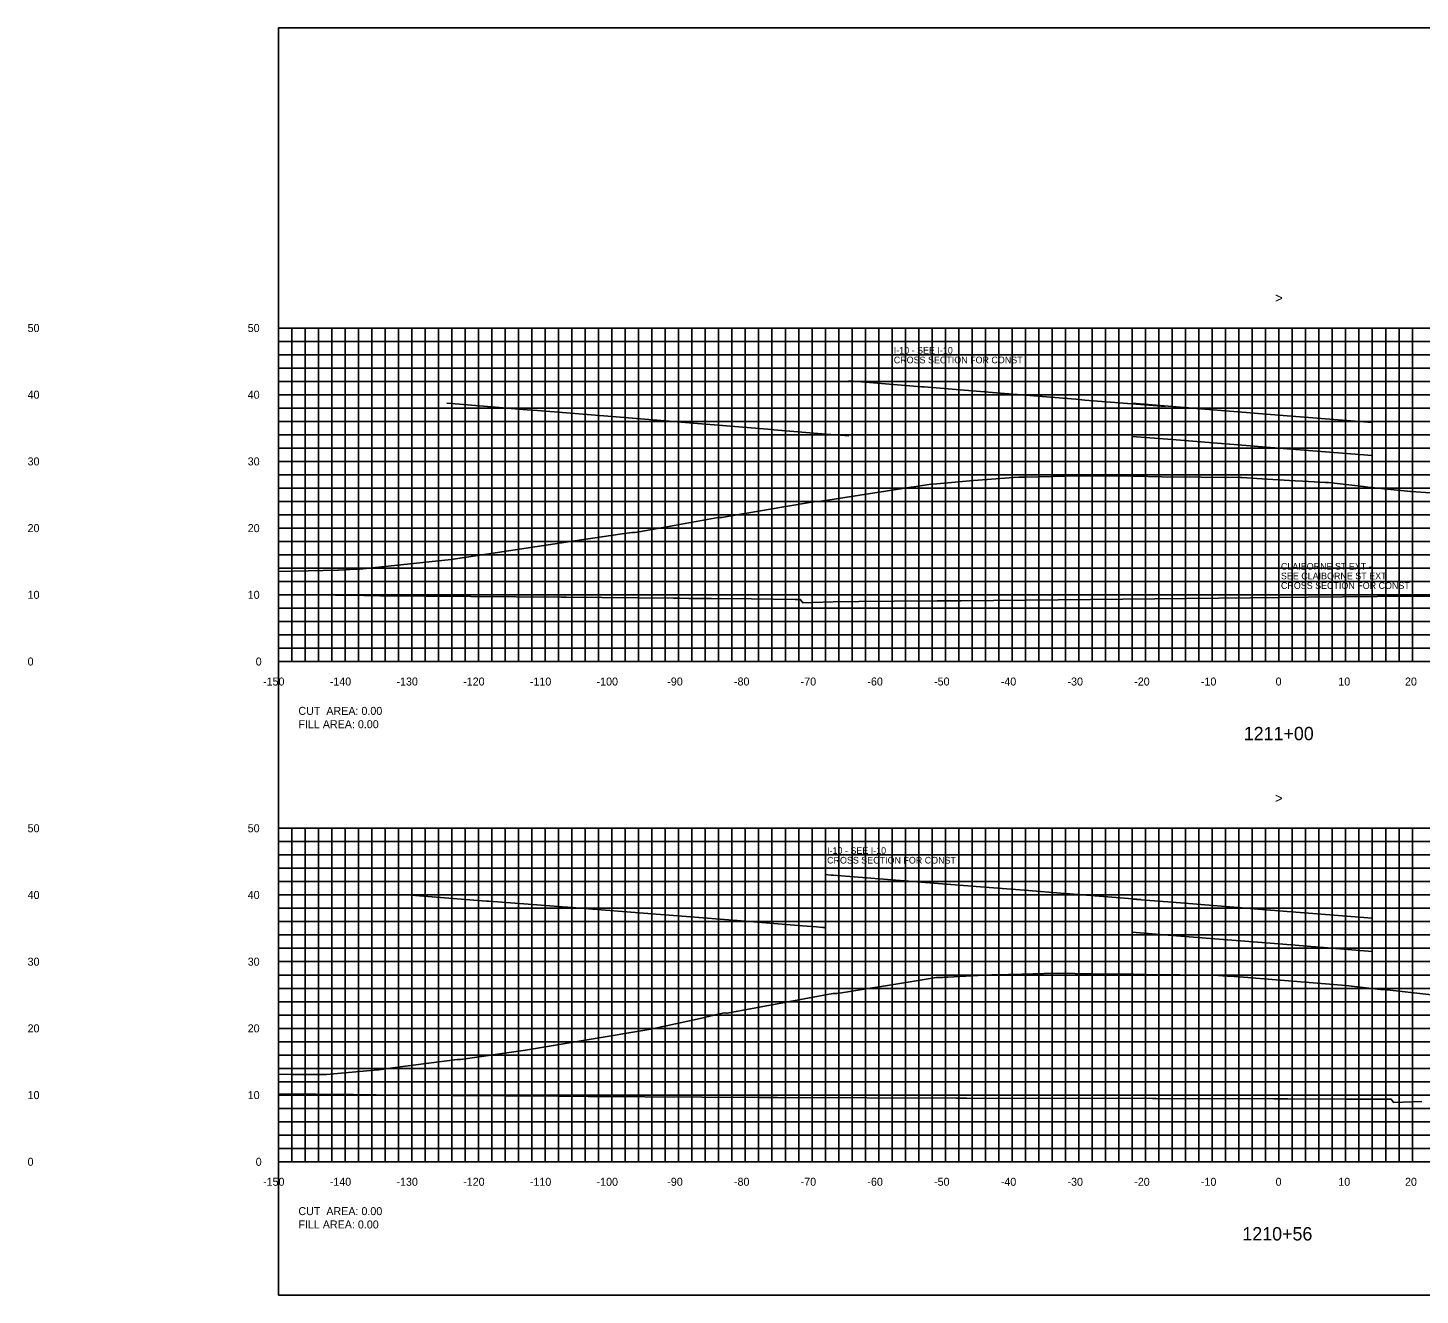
# Model space of a CAD drawing. Extents: x 1797305 to 1804485, y 245831 to 250849.
# Drawn here: x 1804143.4 to 1804352.2, y 250079.4 to 250269.4 of the extents above; entities that cross this region are included whole.
import ezdxf

# ---------------------------------------------------------------- set-up
doc = ezdxf.new("R2010")
doc.units = 0
for name, color, linetype in [('1', 7, 'Continuous'), ('10', 7, 'Continuous'), ('29', 7, 'Continuous'), ('60', 7, 'Continuous'), ('CL-CNST', 7, 'Continuous'), ('EDPV-LINE', 7, 'Continuous'), ('Level 31', 7, 'Continuous'), ('LIMT-CSLINE', 7, 'Continuous'), ('M-ROADS', 7, 'Continuous'), ('SURVEY - DRAINAGE - Area Shapes', 7, 'Continuous')]:
    doc.layers.add(name, color=color, linetype=linetype)

msp = doc.modelspace()

# ---------------------------------------------------------------- linework, layer by layer
msp.add_lwpolyline([(1804181, 250079.43), (1804481, 250079.43), (1804481, 250269.43), (1804181, 250269.43)], close=True)
at = {"layer": '29'}
for p, q in [((1804181, 250224.43), (1804481, 250224.43)), ((1804181, 250174.43), (1804181, 250224.43)), ((1804183, 250174.43), (1804183, 250224.43)), ((1804185, 250174.43), (1804185, 250224.43)), ((1804187, 250174.43), (1804187, 250224.43)), ((1804189, 250174.43), (1804189, 250224.43)), ((1804191, 250174.43), (1804191, 250224.43)), ((1804193, 250174.43), (1804193, 250224.43)), ((1804195, 250174.43), (1804195, 250224.43)), ((1804197, 250174.43), (1804197, 250224.43)), ((1804199, 250174.43), (1804199, 250224.43)), ((1804201, 250174.43), (1804201, 250224.43)), ((1804203, 250174.43), (1804203, 250224.43)), ((1804205, 250174.43), (1804205, 250224.43)), ((1804207, 250174.43), (1804207, 250224.43)), ((1804209, 250174.43), (1804209, 250224.43)), ((1804211, 250174.43), (1804211, 250224.43)), ((1804213, 250174.43), (1804213, 250224.43)), ((1804215, 250174.43), (1804215, 250224.43)), ((1804217, 250174.43), (1804217, 250224.43)), ((1804219, 250174.43), (1804219, 250224.43)), ((1804221, 250174.43), (1804221, 250224.43)), ((1804223, 250174.43), (1804223, 250224.43)), ((1804225, 250174.43), (1804225, 250224.43)), ((1804227, 250174.43), (1804227, 250224.43)), ((1804229, 250174.43), (1804229, 250224.43)), ((1804231, 250174.43), (1804231, 250224.43)), ((1804233, 250174.43), (1804233, 250224.43)), ((1804235, 250174.43), (1804235, 250224.43)), ((1804237, 250174.43), (1804237, 250224.43)), ((1804239, 250174.43), (1804239, 250224.43)), ((1804241, 250174.43), (1804241, 250224.43)), ((1804243, 250174.43), (1804243, 250224.43)), ((1804245, 250174.43), (1804245, 250224.43)), ((1804247, 250174.43), (1804247, 250224.43)), ((1804249, 250174.43), (1804249, 250224.43)), ((1804251, 250174.43), (1804251, 250224.43)), ((1804253, 250174.43), (1804253, 250224.43)), ((1804255, 250174.43), (1804255, 250224.43)), ((1804257, 250174.43), (1804257, 250224.43)), ((1804259, 250174.43), (1804259, 250224.43)), ((1804261, 250174.43), (1804261, 250224.43)), ((1804263, 250174.43), (1804263, 250224.43)), ((1804265, 250174.43), (1804265, 250224.43)), ((1804267, 250174.43), (1804267, 250224.43)), ((1804269, 250174.43), (1804269, 250224.43)), ((1804271, 250174.43), (1804271, 250224.43)), ((1804273, 250174.43), (1804273, 250224.43)), ((1804275, 250174.43), (1804275, 250224.43)), ((1804277, 250174.43), (1804277, 250224.43)), ((1804279, 250174.43), (1804279, 250224.43)), ((1804281, 250174.43), (1804281, 250224.43)), ((1804283, 250174.43), (1804283, 250224.43)), ((1804285, 250174.43), (1804285, 250224.43)), ((1804287, 250174.43), (1804287, 250224.43)), ((1804289, 250174.43), (1804289, 250224.43)), ((1804291, 250174.43), (1804291, 250224.43)), ((1804293, 250174.43), (1804293, 250224.43)), ((1804295, 250174.43), (1804295, 250224.43)), ((1804297, 250174.43), (1804297, 250224.43)), ((1804299, 250174.43), (1804299, 250224.43)), ((1804301, 250174.43), (1804301, 250224.43)), ((1804303, 250174.43), (1804303, 250224.43)), ((1804305, 250174.43), (1804305, 250224.43)), ((1804307, 250174.43), (1804307, 250224.43)), ((1804309, 250174.43), (1804309, 250224.43)), ((1804311, 250174.43), (1804311, 250224.43)), ((1804313, 250174.43), (1804313, 250224.43)), ((1804315, 250174.43), (1804315, 250224.43)), ((1804317, 250174.43), (1804317, 250224.43)), ((1804319, 250174.43), (1804319, 250224.43)), ((1804321, 250174.43), (1804321, 250224.43)), ((1804323, 250174.43), (1804323, 250224.43)), ((1804325, 250174.43), (1804325, 250224.43)), ((1804327, 250174.43), (1804327, 250224.43)), ((1804329, 250174.43), (1804329, 250224.43)), ((1804331, 250174.43), (1804331, 250224.43)), ((1804333, 250174.43), (1804333, 250224.43)), ((1804335, 250174.43), (1804335, 250224.43)), ((1804337, 250174.43), (1804337, 250224.43)), ((1804339, 250174.43), (1804339, 250224.43)), ((1804341, 250174.43), (1804341, 250224.43)), ((1804343, 250174.43), (1804343, 250224.43)), ((1804345, 250174.43), (1804345, 250224.43)), ((1804347, 250174.43), (1804347, 250224.43)), ((1804349, 250174.43), (1804349, 250224.43)), ((1804351, 250174.43), (1804351, 250224.43)), ((1804181, 250222.43), (1804481, 250222.43)), ((1804181, 250220.43), (1804481, 250220.43)), ((1804181, 250218.43), (1804481, 250218.43)), ((1804181, 250216.43), (1804481, 250216.43)), ((1804181, 250214.43), (1804481, 250214.43)), ((1804181, 250212.43), (1804481, 250212.43)), ((1804181, 250210.43), (1804481, 250210.43)), ((1804181, 250208.43), (1804481, 250208.43)), ((1804181, 250206.43), (1804481, 250206.43)), ((1804181, 250204.43), (1804481, 250204.43)), ((1804181, 250202.43), (1804481, 250202.43)), ((1804181, 250200.43), (1804481, 250200.43)), ((1804181, 250198.43), (1804481, 250198.43)), ((1804181, 250196.43), (1804481, 250196.43)), ((1804181, 250194.43), (1804481, 250194.43)), ((1804181, 250192.43), (1804481, 250192.43)), ((1804181, 250190.43), (1804481, 250190.43)), ((1804181, 250188.43), (1804481, 250188.43)), ((1804181, 250186.43), (1804481, 250186.43)), ((1804181, 250184.43), (1804481, 250184.43)), ((1804181, 250182.43), (1804481, 250182.43)), ((1804181, 250180.43), (1804481, 250180.43)), ((1804181, 250178.43), (1804481, 250178.43)), ((1804181, 250176.43), (1804481, 250176.43)), ((1804181, 250174.43), (1804481, 250174.43)), ((1804181, 250149.43), (1804481, 250149.43)), ((1804181, 250099.43), (1804181, 250149.43)), ((1804183, 250099.43), (1804183, 250149.43)), ((1804185, 250099.43), (1804185, 250149.43)), ((1804187, 250099.43), (1804187, 250149.43)), ((1804189, 250099.43), (1804189, 250149.43)), ((1804191, 250099.43), (1804191, 250149.43)), ((1804193, 250099.43), (1804193, 250149.43)), ((1804195, 250099.43), (1804195, 250149.43)), ((1804197, 250099.43), (1804197, 250149.43)), ((1804199, 250099.43), (1804199, 250149.43)), ((1804201, 250099.43), (1804201, 250149.43)), ((1804203, 250099.43), (1804203, 250149.43)), ((1804205, 250099.43), (1804205, 250149.43)), ((1804207, 250099.43), (1804207, 250149.43)), ((1804209, 250099.43), (1804209, 250149.43)), ((1804211, 250099.43), (1804211, 250149.43)), ((1804213, 250099.43), (1804213, 250149.43)), ((1804215, 250099.43), (1804215, 250149.43)), ((1804217, 250099.43), (1804217, 250149.43)), ((1804219, 250099.43), (1804219, 250149.43)), ((1804221, 250099.43), (1804221, 250149.43)), ((1804223, 250099.43), (1804223, 250149.43)), ((1804225, 250099.43), (1804225, 250149.43)), ((1804227, 250099.43), (1804227, 250149.43)), ((1804229, 250099.43), (1804229, 250149.43)), ((1804231, 250099.43), (1804231, 250149.43)), ((1804233, 250099.43), (1804233, 250149.43)), ((1804235, 250099.43), (1804235, 250149.43)), ((1804237, 250099.43), (1804237, 250149.43)), ((1804239, 250099.43), (1804239, 250149.43)), ((1804241, 250099.43), (1804241, 250149.43)), ((1804243, 250099.43), (1804243, 250149.43)), ((1804245, 250099.43), (1804245, 250149.43)), ((1804247, 250099.43), (1804247, 250149.43)), ((1804249, 250099.43), (1804249, 250149.43)), ((1804251, 250099.43), (1804251, 250149.43)), ((1804253, 250099.43), (1804253, 250149.43)), ((1804255, 250099.43), (1804255, 250149.43)), ((1804257, 250099.43), (1804257, 250149.43)), ((1804259, 250099.43), (1804259, 250149.43)), ((1804261, 250099.43), (1804261, 250149.43)), ((1804263, 250099.43), (1804263, 250149.43)), ((1804265, 250099.43), (1804265, 250149.43)), ((1804267, 250099.43), (1804267, 250149.43)), ((1804269, 250099.43), (1804269, 250149.43)), ((1804271, 250099.43), (1804271, 250149.43)), ((1804273, 250099.43), (1804273, 250149.43)), ((1804275, 250099.43), (1804275, 250149.43)), ((1804277, 250099.43), (1804277, 250149.43)), ((1804279, 250099.43), (1804279, 250149.43)), ((1804281, 250099.43), (1804281, 250149.43)), ((1804283, 250099.43), (1804283, 250149.43)), ((1804285, 250099.43), (1804285, 250149.43)), ((1804287, 250099.43), (1804287, 250149.43)), ((1804289, 250099.43), (1804289, 250149.43)), ((1804291, 250099.43), (1804291, 250149.43)), ((1804293, 250099.43), (1804293, 250149.43)), ((1804295, 250099.43), (1804295, 250149.43)), ((1804297, 250099.43), (1804297, 250149.43)), ((1804299, 250099.43), (1804299, 250149.43)), ((1804301, 250099.43), (1804301, 250149.43)), ((1804303, 250099.43), (1804303, 250149.43)), ((1804305, 250099.43), (1804305, 250149.43)), ((1804307, 250099.43), (1804307, 250149.43)), ((1804309, 250099.43), (1804309, 250149.43)), ((1804311, 250099.43), (1804311, 250149.43)), ((1804313, 250099.43), (1804313, 250149.43)), ((1804315, 250099.43), (1804315, 250149.43)), ((1804317, 250099.43), (1804317, 250149.43)), ((1804319, 250099.43), (1804319, 250149.43)), ((1804321, 250099.43), (1804321, 250149.43)), ((1804323, 250099.43), (1804323, 250149.43)), ((1804325, 250099.43), (1804325, 250149.43)), ((1804327, 250099.43), (1804327, 250149.43)), ((1804329, 250099.43), (1804329, 250149.43)), ((1804331, 250099.43), (1804331, 250149.43)), ((1804333, 250099.43), (1804333, 250149.43)), ((1804335, 250099.43), (1804335, 250149.43)), ((1804337, 250099.43), (1804337, 250149.43)), ((1804339, 250099.43), (1804339, 250149.43)), ((1804341, 250099.43), (1804341, 250149.43)), ((1804343, 250099.43), (1804343, 250149.43)), ((1804345, 250099.43), (1804345, 250149.43)), ((1804347, 250099.43), (1804347, 250149.43)), ((1804349, 250099.43), (1804349, 250149.43)), ((1804351, 250099.43), (1804351, 250149.43)), ((1804181, 250147.43), (1804481, 250147.43)), ((1804181, 250145.43), (1804481, 250145.43)), ((1804181, 250143.43), (1804481, 250143.43)), ((1804181, 250141.43), (1804481, 250141.43)), ((1804181, 250139.43), (1804481, 250139.43)), ((1804181, 250137.43), (1804481, 250137.43)), ((1804181, 250135.43), (1804481, 250135.43)), ((1804181, 250133.43), (1804481, 250133.43)), ((1804181, 250131.43), (1804481, 250131.43)), ((1804181, 250129.43), (1804481, 250129.43)), ((1804181, 250127.43), (1804481, 250127.43)), ((1804181, 250125.43), (1804481, 250125.43)), ((1804181, 250123.43), (1804481, 250123.43)), ((1804181, 250121.43), (1804481, 250121.43)), ((1804181, 250119.43), (1804481, 250119.43)), ((1804181, 250117.43), (1804481, 250117.43)), ((1804181, 250115.43), (1804481, 250115.43)), ((1804181, 250113.43), (1804481, 250113.43)), ((1804181, 250111.43), (1804481, 250111.43)), ((1804181, 250109.43), (1804481, 250109.43)), ((1804181, 250107.43), (1804481, 250107.43)), ((1804181, 250105.43), (1804481, 250105.43)), ((1804181, 250103.43), (1804481, 250103.43)), ((1804181, 250101.43), (1804481, 250101.43)), ((1804181, 250099.43), (1804481, 250099.43))]:
    msp.add_line(p, q, dxfattribs=at)
at = {"layer": 'CL-CNST'}
for points in [[(1804266.54, 250216.52), (1804266.56, 250216.52), (1804267.8, 250216.42), (1804277.41, 250215.63), (1804277.83, 250215.6), (1804278.39, 250215.55), (1804289.87, 250214.62), (1804300.56, 250213.74), (1804301.91, 250213.63), (1804312.16, 250212.8), (1804313.95, 250212.65)], [(1804206.26, 250213.17), (1804208.15, 250213.01), (1804218.32, 250212.18), (1804219.82, 250212.06), (1804230.39, 250211.2), (1804231.65, 250211.09), (1804243.24, 250210.15), (1804254.98, 250209.19), (1804255.27, 250209.16), (1804263.05, 250208.53), (1804265.29, 250208.34), (1804266.53, 250208.24), (1804266.54, 250208.24)], [(1804309, 250213.14), (1804315, 250212.66), (1804331, 250211.38), (1804345, 250210.26)], [(1804181, 250184.47), (1804193.81, 250184.34), (1804196.32, 250184.28), (1804223.38, 250184.07), (1804224.14, 250184.06), (1804240.22, 250183.95), (1804241.11, 250183.93), (1804242.51, 250183.9), (1804245.95, 250183.87), (1804251.95, 250183.81), (1804258.48, 250183.75), (1804258.48, 250183.75), (1804258.48, 250183.75), (1804258.66, 250183.75), (1804259.24, 250183.75), (1804259.51, 250183.39), (1804259.62, 250183.25), (1804261.12, 250183.3), (1804264.18, 250183.4), (1804268.03, 250183.43), (1804273.3, 250183.47), (1804279.77, 250183.52), (1804283.38, 250183.55), (1804307.58, 250183.77), (1804326.74, 250183.97), (1804335.39, 250184.06), (1804350.87, 250184.24), (1804363.21, 250184.15)], [(1804262.91, 250142.5), (1804263.87, 250142.42), (1804264.16, 250142.4), (1804266.67, 250142.19), (1804274.2, 250141.61), (1804278, 250141.3), (1804286.24, 250140.66), (1804293.44, 250140.1), (1804298.28, 250139.7), (1804304.68, 250139.2), (1804310.32, 250138.74)], [(1804200.12, 250139.46), (1804200.89, 250139.4), (1804212.22, 250138.52), (1804212.56, 250138.5), (1804221.68, 250137.79), (1804224.18, 250137.59), (1804224.34, 250137.58), (1804238.29, 250136.49), (1804239.58, 250136.39), (1804249.78, 250135.59), (1804251.62, 250135.44), (1804259.57, 250134.81), (1804261.65, 250134.64), (1804262.62, 250134.56), (1804262.9, 250134.54)], [(1804309, 250138.81), (1804315, 250138.33), (1804331, 250137.05), (1804345, 250135.93)], [(1804181, 250109.6), (1804192.26, 250109.5), (1804199.08, 250109.42), (1804222.92, 250109.26), (1804227.46, 250109.22), (1804252.98, 250109.09), (1804255.83, 250109.07), (1804282.65, 250108.97), (1804284.2, 250108.96), (1804312.04, 250108.9), (1804312.58, 250108.9), (1804330.22, 250108.89), (1804330.97, 250108.88), (1804332.34, 250108.86), (1804340.95, 250108.82), (1804347.14, 250108.8), (1804347.14, 250108.8), (1804347.14, 250108.8), (1804347.3, 250108.8), (1804347.84, 250108.8), (1804348.11, 250108.43), (1804348.19, 250108.3), (1804350.94, 250108.41), (1804352.42, 250108.47)]]:
    msp.add_lwpolyline(points, dxfattribs=at)
at = {"layer": 'Level 31'}
for p, q in [((1804180.94, 250224.43), (1804181, 250224.43)), ((1804181, 250174.43), (1804181, 250224.43)), ((1804180.94, 250214.43), (1804181, 250214.43)), ((1804180.94, 250204.43), (1804181, 250204.43)), ((1804180.94, 250194.43), (1804181, 250194.43)), ((1804180.94, 250184.43), (1804181, 250184.43)), ((1804180.94, 250174.43), (1804181, 250174.43)), ((1804181, 250174.43), (1804481, 250174.43)), ((1804181, 250174.37), (1804181, 250174.43)), ((1804191, 250174.37), (1804191, 250174.43)), ((1804201, 250174.37), (1804201, 250174.43)), ((1804211, 250174.37), (1804211, 250174.43)), ((1804221, 250174.37), (1804221, 250174.43)), ((1804231, 250174.37), (1804231, 250174.43)), ((1804241, 250174.37), (1804241, 250174.43)), ((1804251, 250174.37), (1804251, 250174.43)), ((1804261, 250174.37), (1804261, 250174.43)), ((1804271, 250174.37), (1804271, 250174.43)), ((1804281, 250174.37), (1804281, 250174.43)), ((1804291, 250174.37), (1804291, 250174.43)), ((1804301, 250174.37), (1804301, 250174.43)), ((1804311, 250174.37), (1804311, 250174.43)), ((1804321, 250174.37), (1804321, 250174.43)), ((1804331, 250174.37), (1804331, 250174.43)), ((1804341, 250174.37), (1804341, 250174.43)), ((1804351, 250174.37), (1804351, 250174.43)), ((1804180.94, 250149.43), (1804181, 250149.43)), ((1804181, 250099.43), (1804181, 250149.43)), ((1804180.94, 250139.43), (1804181, 250139.43)), ((1804180.94, 250129.43), (1804181, 250129.43)), ((1804180.94, 250119.43), (1804181, 250119.43)), ((1804180.94, 250109.43), (1804181, 250109.43)), ((1804180.94, 250099.43), (1804181, 250099.43)), ((1804181, 250099.43), (1804481, 250099.43)), ((1804181, 250099.37), (1804181, 250099.43)), ((1804191, 250099.37), (1804191, 250099.43)), ((1804201, 250099.37), (1804201, 250099.43)), ((1804211, 250099.37), (1804211, 250099.43)), ((1804221, 250099.37), (1804221, 250099.43)), ((1804231, 250099.37), (1804231, 250099.43)), ((1804241, 250099.37), (1804241, 250099.43)), ((1804251, 250099.37), (1804251, 250099.43)), ((1804261, 250099.37), (1804261, 250099.43)), ((1804271, 250099.37), (1804271, 250099.43)), ((1804281, 250099.37), (1804281, 250099.43)), ((1804291, 250099.37), (1804291, 250099.43)), ((1804301, 250099.37), (1804301, 250099.43)), ((1804311, 250099.37), (1804311, 250099.43)), ((1804321, 250099.37), (1804321, 250099.43)), ((1804331, 250099.37), (1804331, 250099.43)), ((1804341, 250099.37), (1804341, 250099.43)), ((1804351, 250099.37), (1804351, 250099.43))]:
    msp.add_line(p, q, dxfattribs=at)
at = {"layer": 'M-ROADS'}
for points in [[(1804181, 250187.95), (1804189.91, 250188.14), (1804190.03, 250188.14), (1804192.68, 250188.29), (1804193.06, 250188.29), (1804193.2, 250188.29), (1804206.9, 250189.71), (1804225.1, 250192.45), (1804232.53, 250193.59), (1804233.99, 250193.78), (1804234.11, 250193.78), (1804234.51, 250193.79), (1804239.24, 250194.64), (1804246.93, 250196.01), (1804247.24, 250196.02), (1804247.45, 250196.02), (1804256.76, 250197.64), (1804261.53, 250198.43), (1804261.91, 250198.43), (1804262.08, 250198.44), (1804275.87, 250200.59), (1804276.26, 250200.64), (1804278.85, 250201.01), (1804279.17, 250201.01), (1804285.21, 250201.56), (1804287.25, 250201.72), (1804291.2, 250202.04), (1804291.99, 250202.06), (1804292.86, 250202.08), (1804295.11, 250202.13), (1804300.8, 250202.25), (1804302.24, 250202.29), (1804309.18, 250202.2), (1804313.42, 250202.14), (1804325.22, 250202.01), (1804325.39, 250202), (1804325.43, 250202), (1804328.44, 250201.84), (1804330.95, 250201.68), (1804333.42, 250201.53), (1804334.6, 250201.45), (1804337.96, 250201.25), (1804338.36, 250201.25), (1804338.45, 250201.25), (1804343.68, 250200.65), (1804344.34, 250200.58), (1804344.81, 250200.53), (1804347.75, 250200.21), (1804350.25, 250199.95), (1804350.7, 250199.94), (1804350.81, 250199.94), (1804358.01, 250199.43)], [(1804181, 250112.55), (1804182.85, 250112.49), (1804183.24, 250112.49), (1804183.4, 250112.49), (1804188.21, 250112.51), (1804195.92, 250113.23), (1804196.08, 250113.23), (1804198.51, 250113.54), (1804207.78, 250114.75), (1804207.93, 250114.75), (1804208.3, 250114.75), (1804218.03, 250116.17), (1804236.82, 250119.3), (1804244.93, 250121.08), (1804245.02, 250121.09), (1804247.83, 250121.74), (1804248.19, 250121.73), (1804248.3, 250121.73), (1804264.14, 250124.64), (1804264.67, 250124.65), (1804265.14, 250124.73), (1804268.8, 250125.31), (1804272.3, 250125.87), (1804275.71, 250126.41), (1804279.63, 250127.04), (1804279.64, 250127.04), (1804280.03, 250127.08), (1804280.12, 250127.08), (1804280.63, 250127.08), (1804280.82, 250127.09), (1804281.37, 250127.12), (1804286.76, 250127.41), (1804287.95, 250127.44), (1804290.45, 250127.51), (1804290.81, 250127.52), (1804295.81, 250127.65), (1804297.98, 250127.71), (1804302.85, 250127.63), (1804309.19, 250127.54), (1804311.07, 250127.52), (1804321.23, 250127.4), (1804323.28, 250127.28), (1804324.3, 250127.23), (1804325.11, 250127.16), (1804341.05, 250125.85), (1804346.24, 250125.25), (1804346.47, 250125.25), (1804346.77, 250125.24), (1804353.94, 250124.46)]]:
    msp.add_lwpolyline(points, dxfattribs=at)
at = {"layer": 'SURVEY - DRAINAGE - Area Shapes'}
for points in [[(1804345, 250205.3), (1804345, 250210.26), (1804331, 250211.38), (1804315, 250212.66), (1804309, 250213.14), (1804309, 250208.18), (1804315, 250207.7), (1804331, 250206.42)], [(1804345, 250130.97), (1804345, 250135.93), (1804331, 250137.05), (1804315, 250138.33), (1804309, 250138.81), (1804309, 250133.85), (1804315, 250133.37), (1804331, 250132.09)]]:
    msp.add_lwpolyline(points, close=True, dxfattribs=at)

# ---------------------------------------------------------------- texts
at = {"layer": '1'}
for s, p in [('1211+00', (1804325.73, 250162.63)), ('1210+56', (1804325.52, 250087.63))]:
    msp.add_text(s, height=2, dxfattribs=at).set_placement(p)
at = {"layer": '10'}
for s, p in [('-150', (1804178.7, 250170.83)), ('-140', (1804188.7, 250170.83)), ('-130', (1804198.7, 250170.83)), ('-120', (1804208.7, 250170.83)), ('-110', (1804218.7, 250170.83)), ('-100', (1804228.7, 250170.83)), ('-90', (1804239.3, 250170.83)), ('-80', (1804249.3, 250170.83)), ('-70', (1804259.3, 250170.83)), ('-60', (1804269.3, 250170.83)), ('-50', (1804279.3, 250170.83)), ('-40', (1804289.3, 250170.83)), ('-30', (1804299.3, 250170.83)), ('-20', (1804309.3, 250170.83)), ('-10', (1804319.3, 250170.83)), ('0', (1804330.5, 250170.83)), ('10', (1804339.9, 250170.83)), ('20', (1804349.9, 250170.83)), ('-150', (1804178.7, 250095.83)), ('-140', (1804188.7, 250095.83)), ('-130', (1804198.7, 250095.83)), ('-120', (1804208.7, 250095.83)), ('-110', (1804218.7, 250095.83)), ('-100', (1804228.7, 250095.83)), ('-90', (1804239.3, 250095.83)), ('-80', (1804249.3, 250095.83)), ('-70', (1804259.3, 250095.83)), ('-60', (1804269.3, 250095.83)), ('-50', (1804279.3, 250095.83)), ('-40', (1804289.3, 250095.83)), ('-30', (1804299.3, 250095.83)), ('-20', (1804309.3, 250095.83)), ('-10', (1804319.3, 250095.83)), ('0', (1804330.5, 250095.83)), ('10', (1804339.9, 250095.83)), ('20', (1804349.9, 250095.83))]:
    msp.add_text(s, height=1.2, dxfattribs=at).set_placement(p)
at = {"layer": '60'}
for s, p in [('50', (1804143.4, 250223.83)), ('50', (1804176.4, 250223.83)), ('40', (1804143.4, 250213.83)), ('40', (1804176.4, 250213.83)), ('30', (1804143.4, 250203.83)), ('30', (1804176.4, 250203.83)), ('20', (1804143.4, 250193.83)), ('20', (1804176.4, 250193.83)), ('10', (1804143.4, 250183.83)), ('10', (1804176.4, 250183.83)), ('0', (1804143.4, 250173.83)), ('0', (1804177.6, 250173.83)), ('50', (1804143.4, 250148.83)), ('50', (1804176.4, 250148.83)), ('40', (1804143.4, 250138.83)), ('40', (1804176.4, 250138.83)), ('30', (1804143.4, 250128.83)), ('30', (1804176.4, 250128.83)), ('20', (1804143.4, 250118.83)), ('20', (1804176.4, 250118.83)), ('10', (1804143.4, 250108.83)), ('10', (1804176.4, 250108.83)), ('0', (1804143.4, 250098.83)), ('0', (1804177.6, 250098.83))]:
    msp.add_text(s, height=1.2, dxfattribs=at).set_placement(p)
at = {"layer": 'EDPV-LINE'}
for s, p in [('CUT  AREA: 0.00', (1804184, 250166.43)), ('FILL AREA: 0.00', (1804184, 250164.43)), ('CUT  AREA: 0.00', (1804184, 250091.43)), ('FILL AREA: 0.00', (1804184, 250089.43))]:
    msp.add_text(s, height=1.2, dxfattribs=at).set_placement(p)
at = {"layer": 'Level 31'}
for s, height, p in [('>', 1.5, (1804330.39, 250228.2)), ('-', 0.0001, (1804181, 250174.43)), ('>', 1.5, (1804330.39, 250153.2)), ('-', 0.0001, (1804181, 250099.43))]:
    msp.add_text(s, height=height, dxfattribs=at).set_placement(p)
at = {"layer": 'LIMT-CSLINE'}
for s, p in [('I-10 - SEE I-10', (1804273.26, 250220.59)), ('CROSS SECTION FOR CONST ', (1804273.26, 250219.14)), ('SEE CLAIBORNE ST EXT', (1804331.3, 250186.76)), ('CLAIBORNE ST EXT -', (1804331.3, 250188.2)), ('CROSS SECTION FOR CONST ', (1804331.3, 250185.32)), ('I-10 - SEE I-10', (1804263.26, 250145.59)), ('CROSS SECTION FOR CONST ', (1804263.26, 250144.14))]:
    msp.add_text(s, height=1, dxfattribs=at).set_placement(p)

doc.saveas('drawing.dxf')
